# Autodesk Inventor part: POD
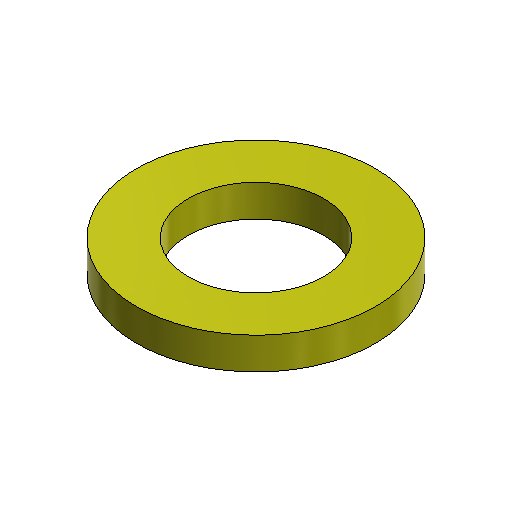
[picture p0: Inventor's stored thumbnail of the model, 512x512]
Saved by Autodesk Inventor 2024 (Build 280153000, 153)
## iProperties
Company: ATC
Shininess: 20.0
Length Units: 11269
Angle Units: 11279
Time Units: 11290
Mass Units: 11283
Length Display Precision: 3
Angle Display Precision: 2
Compacted: True
Created: 2023-03
Part Number: POD
Document SubType Name: Modeling
Designer: Andrzej Jaskulski
Material: Kurs-AJ
Density: 1 g/cm^3
Mass: 0.239939 g
Surface Area: 3.87594 cm^2
Volume: 0.239939 cm^3
Appearance: Żółta
Checked By: A.J.
Engr Approved By: Andrzej Jaskulski
Mfg Approved By: Andrzej Jaskulski
Authority: A.J.
Density: 0.0
Volumn: 0.0
Area: 0.0
PropertySet Name: Model Information
Control State: 0
Master: False
Checked Out: False
Title: A.J.: Kurs R2024-MEP
Author: Andrzej Jaskulski
Revision Number: 1/24
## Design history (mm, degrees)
sketch "Sketch1"
  geometry: C1 r 4.25 at (0, 0); C2 r 7.5 at (0, 0)
  constraints: 2 centre point, 1 coincident
  dimensions: "d2" = 8.5 diameter of C1; "d3" = 15 diameter of C2
extrude "Extrusion1" new body sketch "Sketch1" distance "d0" = 2; taper "d1" = 0 deg
node "Bryła1"
node "Korpusy bryłowe"
node "Korpusy powierzchniowe"
